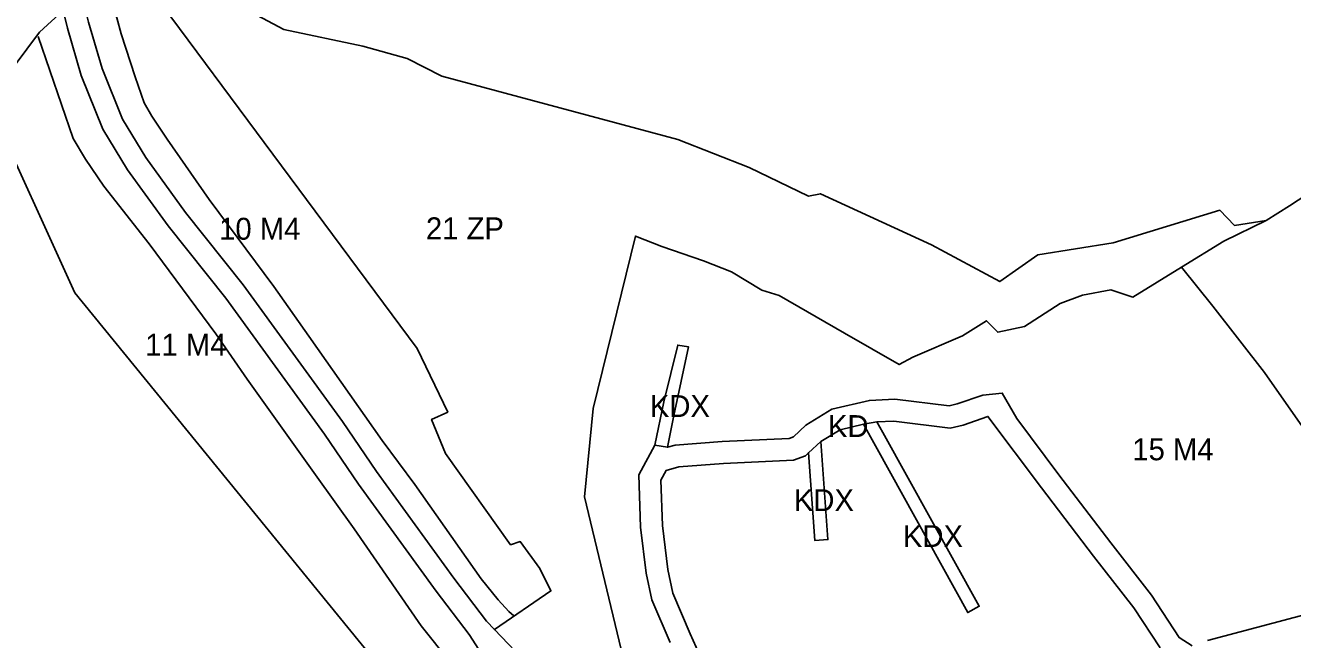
# Model space of a CAD drawing. Extents: x 7437831 to 7440315, y 5545798 to 5547888.
# Drawn here: x 7439385 to 7439964, y 5547256 to 5547537 of the extents above; entities that cross this region are included whole.
import ezdxf

# ---------------------------------------------------------------- set-up
doc = ezdxf.new("R2010")
doc.units = 0
for name, color, linetype in [('linie_rozgraniczajace', 7, 'Continuous'), ('linie_zabudowy_nieprzekraczalne', 7, 'Continuous'), ('oznaczenia_przeznaczen', 7, 'Continuous')]:
    doc.layers.add(name, color=color, linetype=linetype)

msp = doc.modelspace()

# ---------------------------------------------------------------- linework, layer by layer
at = {"layer": 'linie_rozgraniczajace'}
for points in [[(7439721.65, 5547203.82), (7439715.2, 5547208.23), (7439703.63, 5547212.64), (7439687.89, 5547214.81), (7439672.7, 5547216.33), (7439659.7, 5547218.31), (7439640.95, 5547223.59), (7439620.79, 5547231.98), (7439593.65, 5547250.12), (7439592.45, 5547251.78), (7439587.97, 5547258.66), (7439572.92, 5547278.45), (7439537.42, 5547327.35), (7439521.84, 5547350.29), (7439476.68, 5547412.41), (7439450.29, 5547445.41), (7439431.75, 5547471.05), (7439420.51, 5547489.6), (7439410.65, 5547514.06), (7439404.34, 5547535.78), (7439402.31, 5547543.75), (7439398.38, 5547559.18), (7439395.54, 5547573.5), (7439401.86, 5547591.35)], [(7439608.97, 5547251.12), (7439599.56, 5547260.93), (7439625.35, 5547278.65), (7439620.28, 5547288.8), (7439611.33, 5547301.12), (7439606.95, 5547299.68), (7439577.13, 5547341.39), (7439570.79, 5547356.99), (7439578.18, 5547360.3), (7439564.25, 5547389.36), (7439440.1, 5547556.51)], [(7439471.38, 5547552.25), (7439503.19, 5547535.09), (7439539.41, 5547527.56), (7439559.57, 5547521.92), (7439575.52, 5547513.79), (7439683.33, 5547484.8), (7439716.04, 5547472.02), (7439743.13, 5547458.96), (7439748.56, 5547460.08), (7439799.37, 5547436.66), (7439830.68, 5547419.95), (7439847.96, 5547432.13), (7439882.41, 5547437.68), (7439931.2, 5547452.55), (7439937.91, 5547445.51), (7439952.43, 5547447.79), (7439933.08, 5547438.36), (7439913.72, 5547426.48), (7439891.47, 5547412.84), (7439881.38, 5547416.17), (7439868.35, 5547413.68), (7439858.19, 5547409.96), (7439841.89, 5547399.35), (7439829.65, 5547396.77), (7439824.48, 5547402.03), (7439813.52, 5547395.17), (7439790.9, 5547385.34), (7439784.57, 5547382.06), (7439759.59, 5547396.43), (7439729.65, 5547413.52), (7439721.76, 5547416.09), (7439707.87, 5547424.44), (7439695.14, 5547429.43), (7439676.01, 5547435.93), (7439664, 5547440.72), (7439644.71, 5547361.99), (7439640.75, 5547321.64), (7439657.53, 5547251.88)], [(7439413.99, 5547538.42), (7439420.12, 5547517.33), (7439429.48, 5547494.08), (7439440.09, 5547476.57), (7439458.25, 5547451.46), (7439484.64, 5547418.47), (7439530.02, 5547356.04), (7439545.6, 5547333.1), (7439580.95, 5547284.41), (7439595.93, 5547264.72), (7439599.56, 5547260.93), (7439608.97, 5547251.12)], [(7439989.21, 5547324.61), (7439951.69, 5547378.41), (7439927.94, 5547408.69), (7439913.72, 5547426.48), (7439933.08, 5547438.36), (7439952.43, 5547447.79), (7439963.01, 5547454.6), (7439991.67, 5547473.21)], [(7439657.53, 5547251.88), (7439640.75, 5547321.64), (7439644.71, 5547361.99), (7439664, 5547440.72), (7439676.01, 5547435.93), (7439695.14, 5547429.43), (7439707.87, 5547424.44), (7439721.76, 5547416.09), (7439729.65, 5547413.52), (7439759.59, 5547396.43), (7439784.57, 5547382.06), (7439790.9, 5547385.34), (7439813.52, 5547395.17), (7439824.48, 5547402.03), (7439829.65, 5547396.77), (7439841.89, 5547399.35), (7439858.19, 5547409.96), (7439868.35, 5547413.68), (7439881.38, 5547416.17), (7439891.47, 5547412.84), (7439913.72, 5547426.48), (7439927.94, 5547408.69), (7439951.69, 5547378.41), (7439989.21, 5547324.61)], [(7439918.53, 5547253.45), (7439912.61, 5547257.28), (7439899.98, 5547276.7), (7439881.32, 5547300.58), (7439857.66, 5547331.64), (7439838.38, 5547357.36), (7439831.75, 5547368.99), (7439822.82, 5547368.08), (7439811.12, 5547364.02), (7439807.41, 5547363.18), (7439782.54, 5547366.24), (7439770.95, 5547365.68), (7439753.82, 5547361.58), (7439741.84, 5547354.39), (7439736.2, 5547348.97), (7439734.25, 5547348.24), (7439703.73, 5547346.87), (7439682.19, 5547345.2), (7439678.59, 5547344.22), (7439681.55, 5547358.78), (7439688.23, 5547390.14), (7439683.35, 5547390.94), (7439677.03, 5547364.99), (7439672.87, 5547345.23), (7439665.62, 5547331.61), (7439666.37, 5547307.75), (7439668.95, 5547286.76), (7439671.52, 5547274.57), (7439679.85, 5547254.99)], [(7439679.85, 5547254.99), (7439671.52, 5547274.57), (7439668.95, 5547286.76), (7439666.37, 5547307.75), (7439665.62, 5547331.61), (7439672.87, 5547345.23), (7439678.59, 5547344.22), (7439682.19, 5547345.2), (7439703.73, 5547346.87), (7439734.25, 5547348.24), (7439736.2, 5547348.97), (7439741.84, 5547354.39), (7439753.82, 5547361.58), (7439770.95, 5547365.68), (7439782.54, 5547366.24), (7439807.41, 5547363.18), (7439811.12, 5547364.02), (7439822.82, 5547368.08), (7439831.75, 5547368.99), (7439838.38, 5547357.36), (7439857.66, 5547331.64), (7439881.32, 5547300.58), (7439899.98, 5547276.7), (7439912.61, 5547257.28), (7439918.53, 5547253.45)], [(7439903.96, 5547252.55), (7439891.86, 5547270.85), (7439873.4, 5547294.47), (7439849.66, 5547325.65), (7439825.17, 5547358.31), (7439813.87, 5547354.39), (7439807.92, 5547353.04), (7439782.17, 5547356.21), (7439774.37, 5547355.84), (7439768.22, 5547354.75), (7439757.65, 5547352.21), (7439748.77, 5547346.88), (7439743.12, 5547341.75), (7439741.78, 5547340.38), (7439736.27, 5547338.32), (7439704.34, 5547336.89), (7439683.92, 5547335.31), (7439678.05, 5547333.7), (7439675.69, 5547329.26), (7439676.35, 5547308.52), (7439678.82, 5547288.4), (7439681.1, 5547277.59), (7439689.01, 5547258.99), (7439705.56, 5547222.46)], [(7439705.56, 5547222.46), (7439689.01, 5547258.99), (7439681.1, 5547277.59), (7439678.82, 5547288.4), (7439676.35, 5547308.52), (7439675.69, 5547329.26), (7439678.05, 5547333.7), (7439683.92, 5547335.31), (7439704.34, 5547336.89), (7439736.27, 5547338.32), (7439741.78, 5547340.38), (7439743.12, 5547341.75), (7439746.01, 5547301.65), (7439752, 5547302.08), (7439748.77, 5547346.88), (7439757.65, 5547352.21), (7439768.22, 5547354.75), (7439815.96, 5547268.71), (7439821.21, 5547271.62), (7439777.15, 5547351.01), (7439774.37, 5547355.84), (7439782.17, 5547356.21), (7439807.92, 5547353.04), (7439813.87, 5547354.39), (7439825.17, 5547358.31), (7439849.66, 5547325.65), (7439873.4, 5547294.47), (7439891.86, 5547270.85), (7439903.96, 5547252.55)], [(7439995.02, 5547274.44), (7439925.61, 5547255.95)], [(7439925.61, 5547255.95), (7439995.02, 5547274.44)]]:
    msp.add_lwpolyline(points, dxfattribs=at)
for points in [[(7439380.63, 5547586.73), (7439395.54, 5547573.5), (7439398.38, 5547559.18), (7439402.31, 5547543.75), (7439391.54, 5547533.89), (7439367.76, 5547502.29), (7439407.73, 5547414.82), (7439556.07, 5547232.92), (7439403.12, 5547142.44), (7439397.35, 5547140.99), (7439384.59, 5547156.64), (7439386.01, 5547165.4), (7439368.08, 5547186.09), (7439340.2, 5547206.42), (7439325.09, 5547222.17), (7439296.32, 5547254.08), (7439269.71, 5547290.21), (7439250.62, 5547346.08), (7439230.35, 5547407.55), (7439221.74, 5547433.66), (7439210.84, 5547476.54), (7439207.87, 5547510.17), (7439190.23, 5547565.03), (7439189.02, 5547572.47)], [(7439412.26, 5547545.22), (7439440.1, 5547556.51), (7439564.25, 5547389.36), (7439578.18, 5547360.3), (7439570.79, 5547356.99), (7439577.13, 5547341.39), (7439606.95, 5547299.68), (7439611.33, 5547301.12), (7439620.28, 5547288.8), (7439625.35, 5547278.65), (7439599.56, 5547260.93), (7439595.93, 5547264.72), (7439580.95, 5547284.41), (7439545.6, 5547333.1), (7439530.02, 5547356.04), (7439484.64, 5547418.47), (7439458.25, 5547451.46), (7439440.09, 5547476.57), (7439429.48, 5547494.08), (7439420.12, 5547517.33), (7439413.99, 5547538.42)], [(7439402.31, 5547543.75), (7439404.34, 5547535.78), (7439410.65, 5547514.06), (7439420.51, 5547489.6), (7439431.75, 5547471.05), (7439450.29, 5547445.41), (7439476.68, 5547412.41), (7439521.84, 5547350.29), (7439537.42, 5547327.35), (7439572.92, 5547278.45), (7439587.97, 5547258.66), (7439592.45, 5547251.78), (7439556.07, 5547232.92), (7439407.73, 5547414.82), (7439367.76, 5547502.29), (7439391.54, 5547533.89)], [(7439677.03, 5547364.99), (7439683.35, 5547390.94), (7439688.23, 5547390.14), (7439681.55, 5547358.78), (7439678.59, 5547344.22), (7439672.87, 5547345.23)], [(7439774.37, 5547355.84), (7439777.15, 5547351.01), (7439821.21, 5547271.62), (7439815.96, 5547268.71), (7439768.22, 5547354.75)], [(7439748.77, 5547346.88), (7439752, 5547302.08), (7439746.01, 5547301.65), (7439743.12, 5547341.75)]]:
    msp.add_lwpolyline(points, close=True, dxfattribs=at)
at = {"layer": 'linie_zabudowy_nieprzekraczalne'}
for points in [[(7439424.29, 5547550.1), (7439424.94, 5547547.74), (7439428.9, 5547533.11), (7439435.26, 5547513.47), (7439439.39, 5547501.67), (7439442.96, 5547495.57), (7439449.84, 5547484.95), (7439469.12, 5547457.46), (7439498.64, 5547417.63), (7439514.66, 5547395.01), (7439548.2, 5547347.35), (7439563.2, 5547327.19), (7439593.48, 5547284.16), (7439601.31, 5547274.6), (7439606.19, 5547269.18), (7439608.41, 5547267.21)], [(7439579.34, 5547246.12), (7439566.04, 5547262.64), (7439535.41, 5547306.94), (7439517.66, 5547331.6), (7439486.5, 5547375.43), (7439472.16, 5547396.12), (7439441.63, 5547437.13), (7439420.89, 5547463.48), (7439412.5, 5547475.89), (7439406.96, 5547485.33), (7439390.88, 5547531.96)]]:
    msp.add_lwpolyline(points, dxfattribs=at)

# ---------------------------------------------------------------- texts
at = {"layer": 'oznaczenia_przeznaczen'}
for s, p in [('10 M4', (7439473.6605, 5547439.08)), ('21 ZP', (7439568.1983, 5547439.29)), ('11 M4', (7439439.8405, 5547386.1)), ('KDX', (7439670.5743, 5547358.08)), ('KD', (7439752.0127, 5547348.92)), ('15 M4', (7439891.1805, 5547338.31)), ('KDX', (7439736.4243, 5547315.08)), ('KDX', (7439786.2743, 5547298.65))]:
    msp.add_text(s, height=10, dxfattribs=at).set_placement(p)

doc.saveas('drawing.dxf')
